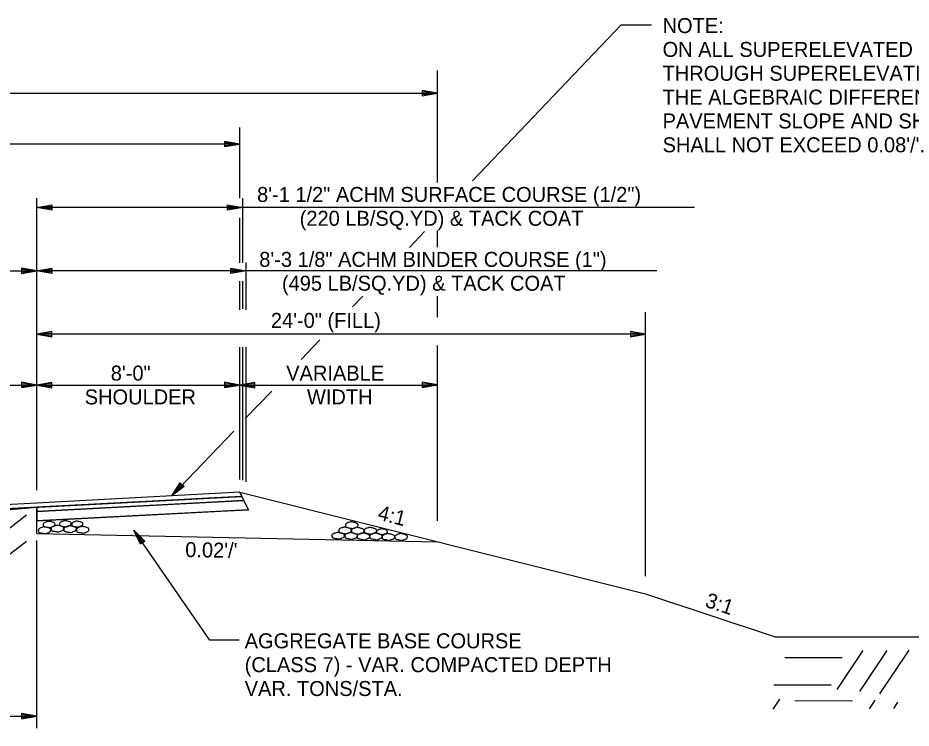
# Model space of a CAD drawing. Extents: x 1398183 to 1398373, y 1967240 to 1968889.
# Drawn here: x 1398269.99 to 1398305.19, y 1967927.15 to 1967955.14 of the extents above; entities that cross this region are included whole.
import ezdxf

# ---------------------------------------------------------------- set-up
doc = ezdxf.new("R2010")
doc.units = 0
for name, color, linetype in [('1', 7, 'Continuous'), ('10', 7, 'Continuous'), ('19', 7, 'Continuous'), ('42', 7, 'Continuous'), ('9', 7, 'Continuous'), ('Level 1', 7, 'Continuous')]:
    doc.layers.add(name, color=color, linetype=linetype)

# ---------------------------------------------------------------- blocks, each defined once
blk = doc.blocks.new('ROCKS')
at = {"layer": '1'}
blk.add_spline([(0.013, 0.06), (0.053, 0.053), (0.107, 0.033), (0.133, 0.013), (0.133, -0.007), (0.12, -0.033), (0.107, -0.04), (0.073, -0.053), (0.033, -0.067), (0.013, -0.067), (-0.02, -0.06), (-0.06, -0.053), (-0.087, -0.047), (-0.113, -0.02), (-0.113, -0.007), (-0.107, 0.02), (-0.087, 0.033), (-0.067, 0.047), (-0.033, 0.053), (-0.02, 0.06), (0.013, 0.06)], degree=3, dxfattribs=at)

msp = doc.modelspace()

# ---------------------------------------------------------------- linework, layer by layer
at = {"layer": '19'}
for p, q in [((1398286.524, 1967948.65), (1398286.524, 1967953.065)), ((1398222.727, 1967952.173), (1398286.524, 1967952.173)), ((1398285.924, 1967952.279), (1398285.924, 1967952.069)), ((1398286.524, 1967952.174), (1398285.924, 1967952.279)), ((1398286.364, 1967952.189), (1398285.924, 1967952.224)), ((1398285.924, 1967952.069), (1398286.524, 1967952.174)), ((1398285.924, 1967952.119), (1398286.364, 1967952.159)), ((1398278.734, 1967948.033), (1398278.734, 1967950.821)), ((1398278.734, 1967950.173), (1398228.734, 1967950.173)), ((1398278.134, 1967950.278), (1398278.134, 1967950.068)), ((1398278.734, 1967950.173), (1398278.134, 1967950.278)), ((1398278.574, 1967950.188), (1398278.134, 1967950.223)), ((1398278.134, 1967950.068), (1398278.734, 1967950.173)), ((1398278.134, 1967950.118), (1398278.574, 1967950.158)), ((1398270.731, 1967936.522), (1398270.731, 1967948.033)), ((1398278.853, 1967945.485), (1398278.853, 1967948.033)), ((1398270.73, 1967947.673), (1398271.33, 1967947.779)), ((1398271.33, 1967947.569), (1398270.73, 1967947.673)), ((1398296.658, 1967947.673), (1398270.73, 1967947.673)), ((1398270.89, 1967947.688), (1398271.33, 1967947.724)), ((1398271.33, 1967947.619), (1398270.89, 1967947.658)), ((1398271.33, 1967947.779), (1398271.33, 1967947.569)), ((1398278.253, 1967947.568), (1398278.253, 1967947.778)), ((1398278.253, 1967947.778), (1398278.853, 1967947.673)), ((1398278.253, 1967947.723), (1398278.693, 1967947.688)), ((1398278.853, 1967947.673), (1398278.253, 1967947.568)), ((1398278.693, 1967947.658), (1398278.253, 1967947.618)), ((1398278.734, 1967945.495), (1398278.734, 1967947.258)), ((1398286.524, 1967946.111), (1398286.524, 1967946.769)), ((1398278.985, 1967943.63), (1398278.985, 1967945.498)), ((1398217.678, 1967945.173), (1398270.731, 1967945.173)), ((1398270.132, 1967945.279), (1398270.132, 1967945.069)), ((1398270.732, 1967945.173), (1398270.132, 1967945.279)), ((1398270.572, 1967945.188), (1398270.132, 1967945.224)), ((1398270.132, 1967945.069), (1398270.732, 1967945.173)), ((1398270.132, 1967945.119), (1398270.572, 1967945.158)), ((1398270.73, 1967945.173), (1398271.33, 1967945.279)), ((1398271.33, 1967945.069), (1398270.73, 1967945.173)), ((1398295.174, 1967945.173), (1398270.73, 1967945.173)), ((1398270.89, 1967945.188), (1398271.33, 1967945.224)), ((1398271.33, 1967945.119), (1398270.89, 1967945.158)), ((1398271.33, 1967945.279), (1398271.33, 1967945.069)), ((1398278.385, 1967945.068), (1398278.385, 1967945.278)), ((1398278.385, 1967945.278), (1398278.985, 1967945.173)), ((1398278.385, 1967945.223), (1398278.825, 1967945.188)), ((1398278.985, 1967945.173), (1398278.385, 1967945.068)), ((1398278.825, 1967945.158), (1398278.385, 1967945.118)), ((1398278.734, 1967943.64), (1398278.734, 1967944.771)), ((1398278.853, 1967943.671), (1398278.853, 1967944.771)), ((1398286.524, 1967943.344), (1398286.524, 1967944.169)), ((1398294.731, 1967933.141), (1398294.731, 1967943.549)), ((1398271.331, 1967942.778), (1398270.731, 1967942.673)), ((1398294.731, 1967942.673), (1398270.731, 1967942.673)), ((1398270.731, 1967942.673), (1398271.331, 1967942.568)), ((1398271.331, 1967942.723), (1398270.891, 1967942.688)), ((1398270.891, 1967942.658), (1398271.331, 1967942.618)), ((1398271.331, 1967942.568), (1398271.331, 1967942.778)), ((1398294.131, 1967942.778), (1398294.131, 1967942.568)), ((1398294.731, 1967942.673), (1398294.131, 1967942.778)), ((1398294.571, 1967942.688), (1398294.131, 1967942.723)), ((1398294.131, 1967942.568), (1398294.731, 1967942.673)), ((1398294.131, 1967942.618), (1398294.571, 1967942.658)), ((1398286.524, 1967935.321), (1398286.524, 1967942.228)), ((1398278.731, 1967936.946), (1398278.731, 1967942.165)), ((1398278.853, 1967936.923), (1398278.853, 1967942.165)), ((1398278.985, 1967936.86), (1398278.985, 1967942.165)), ((1398258.731, 1967940.673), (1398270.731, 1967940.673)), ((1398270.131, 1967940.779), (1398270.131, 1967940.569)), ((1398270.731, 1967940.673), (1398270.131, 1967940.779)), ((1398270.571, 1967940.688), (1398270.131, 1967940.724)), ((1398270.131, 1967940.569), (1398270.731, 1967940.673)), ((1398270.131, 1967940.619), (1398270.571, 1967940.658)), ((1398271.331, 1967940.778), (1398270.731, 1967940.673)), ((1398270.731, 1967940.673), (1398271.331, 1967940.568)), ((1398270.731, 1967940.673), (1398278.731, 1967940.673)), ((1398271.331, 1967940.723), (1398270.891, 1967940.688)), ((1398270.891, 1967940.658), (1398271.331, 1967940.618)), ((1398271.331, 1967940.568), (1398271.331, 1967940.778)), ((1398278.131, 1967940.779), (1398278.131, 1967940.569)), ((1398278.731, 1967940.673), (1398278.131, 1967940.779)), ((1398278.571, 1967940.688), (1398278.131, 1967940.724)), ((1398278.131, 1967940.569), (1398278.731, 1967940.673)), ((1398278.131, 1967940.619), (1398278.571, 1967940.658)), ((1398279.331, 1967940.778), (1398278.731, 1967940.673)), ((1398278.731, 1967940.673), (1398286.524, 1967940.673)), ((1398278.731, 1967940.673), (1398279.331, 1967940.568)), ((1398279.331, 1967940.723), (1398278.891, 1967940.688)), ((1398278.891, 1967940.658), (1398279.331, 1967940.618)), ((1398279.331, 1967940.568), (1398279.331, 1967940.778)), ((1398285.924, 1967940.779), (1398285.924, 1967940.569)), ((1398286.524, 1967940.674), (1398285.924, 1967940.779)), ((1398286.364, 1967940.689), (1398285.924, 1967940.724)), ((1398285.924, 1967940.569), (1398286.524, 1967940.674)), ((1398285.924, 1967940.619), (1398286.364, 1967940.659)), ((1398276.054, 1967936.304), (1398276.386, 1967936.815)), ((1398276.538, 1967936.672), (1398276.054, 1967936.304)), ((1398276.154, 1967936.429), (1398276.423, 1967936.777)), ((1398276.501, 1967936.705), (1398276.175, 1967936.41)), ((1398276.386, 1967936.815), (1398276.538, 1967936.672)), ((1398278.731, 1967936.446), (1398294.731, 1967932.446)), ((1398278.731, 1967936.446), (1398278.813, 1967936.284)), ((1398278.813, 1967936.284), (1398278.894, 1967936.121)), ((1398277.971, 1967936.074), (1398270.731, 1967935.689)), ((1398278.894, 1967936.121), (1398277.971, 1967936.074)), ((1398278.894, 1967936.121), (1398279.077, 1967935.756)), ((1398279.077, 1967935.756), (1398278.894, 1967936.121)), ((1398270.334, 1967935.537), (1398267.632, 1967933.469)), ((1398270.731, 1967934.814), (1398270.731, 1967935.847)), ((1398270.731, 1967935.314), (1398277.99, 1967935.699)), ((1398270.731, 1967935.689), (1398270.731, 1967935.314)), ((1398277.99, 1967935.699), (1398279.077, 1967935.756)), ((1398270.731, 1967934.814), (1398286.524, 1967934.498)), ((1398274.819, 1967934.396), (1398274.566, 1967934.948)), ((1398274.566, 1967934.948), (1398274.991, 1967934.512)), ((1398277.558, 1967930.617), (1398274.566, 1967934.948)), ((1398274.859, 1967934.424), (1398274.642, 1967934.808)), ((1398274.666, 1967934.824), (1398274.946, 1967934.485)), ((1398270.334, 1967934.51), (1398267.652, 1967932.457)), ((1398270.731, 1967927.148), (1398270.731, 1967934.539)), ((1398274.991, 1967934.512), (1398274.819, 1967934.396)), ((1398294.731, 1967932.446), (1398299.832, 1967930.746)), ((1398278.709, 1967930.617), (1398277.558, 1967930.617)), ((1398246.731, 1967927.618), (1398270.731, 1967927.618)), ((1398270.131, 1967927.723), (1398270.131, 1967927.513)), ((1398270.731, 1967927.618), (1398270.131, 1967927.723)), ((1398270.571, 1967927.633), (1398270.131, 1967927.668)), ((1398270.131, 1967927.513), (1398270.731, 1967927.618)), ((1398270.131, 1967927.563), (1398270.571, 1967927.603))]:
    msp.add_line(p, q, dxfattribs=at)
for points in [[(1398294.964, 1967954.862), (1398293.755, 1967954.862), (1398287.901, 1967948.718)], [(1398286.016, 1967946.719), (1398285.418, 1967946.095)], [(1398283.582, 1967944.18), (1398283.174, 1967943.754)], [(1398281.896, 1967942.457), (1398281.158, 1967941.679)], [(1398279.998, 1967940.433), (1398279.998, 1967940.433), (1398278.952, 1967939.347)], [(1398278.495, 1967938.859), (1398278.495, 1967938.859), (1398276.054, 1967936.304)], [(1398278.731, 1967936.446), (1398270.731, 1967936.022), (1398258.731, 1967935.386), (1398246.731, 1967934.75), (1398234.731, 1967934.114), (1398228.731, 1967933.796)], [(1398278.813, 1967936.284), (1398270.731, 1967935.855), (1398258.731, 1967935.219), (1398246.731, 1967934.583), (1398234.731, 1967933.947), (1398228.731, 1967933.629)], [(1398278.894, 1967936.121), (1398270.731, 1967935.689)], [(1398279.077, 1967935.756), (1398270.731, 1967935.314)]]:
    msp.add_lwpolyline(points, dxfattribs=at)
for points in [[(1398228.646, 1967933.626), (1398234.646, 1967933.944), (1398258.722, 1967935.214), (1398270.817, 1967935.852), (1398278.813, 1967936.284), (1398278.731, 1967936.446), (1398270.731, 1967936.022), (1398258.731, 1967935.386), (1398234.731, 1967934.114), (1398228.731, 1967933.796)], [(1398270.731, 1967935.689), (1398276.376, 1967935.989), (1398278.894, 1967936.121), (1398278.813, 1967936.284), (1398277.735, 1967936.227), (1398270.731, 1967935.847)]]:
    msp.add_lwpolyline(points, close=True, dxfattribs=at)
at = {"layer": '42'}
for points in [[(1398270.731, 1967935.841), (1398266.421, 1967935.468), (1398258.785, 1967935.079), (1398249.763, 1967934.595), (1398246.74, 1967934.584), (1398246.731, 1967934.583)], [(1398299.832, 1967930.746), (1398306.118, 1967930.746), (1398309.834, 1967930.695)]]:
    msp.add_lwpolyline(points, dxfattribs=at)
at = {"layer": '9'}
for p, q in [((1398302.48, 1967929.918), (1398300.218, 1967929.924)), ((1398303.287, 1967930.208), (1398302.264, 1967928.674)), ((1398304.239, 1967930.213), (1398303.154, 1967928.586)), ((1398305.099, 1967930.218), (1398303.952, 1967928.498)), ((1398302.041, 1967928.839), (1398299.779, 1967928.845)), ((1398300.004, 1967928.29), (1398299.74, 1967927.894)), ((1398302.878, 1967928.213), (1398300.616, 1967928.219)), ((1398303.768, 1967928.256), (1398303.541, 1967927.915)), ((1398304.658, 1967928.168), (1398304.493, 1967927.92))]:
    msp.add_line(p, q, dxfattribs=at)

# ---------------------------------------------------------------- block references
at = {"layer": 'Level 1'}
for p, xscale, yscale, rotation in [((1398271.201, 1967935.184), 1.8866375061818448, 1.886637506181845, 1.8263814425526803), ((1398271.842, 1967935.208), 1.851115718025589, 1.851115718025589, 1.8263814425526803), ((1398272.317, 1967935.195), 1.773922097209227, 1.773922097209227, 1.8263814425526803), ((1398283.133, 1967935.154), 2.011654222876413, 2.0116542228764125, -0.17361855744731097), ((1398271.023, 1967934.953), 2.011654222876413, 2.011654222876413, 1.8263814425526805), ((1398271.531, 1967935.016), 2.011654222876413, 2.011654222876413, 1.8263814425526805), ((1398272.025, 1967934.997), 2.011654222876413, 2.011654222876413, 1.8263814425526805), ((1398272.522, 1967934.972), 2.011654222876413, 2.011654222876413, 1.8263814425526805), ((1398282.594, 1967934.739), 2.011654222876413, 2.0116542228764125, -0.17361855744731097), ((1398282.594, 1967934.739), 2.011654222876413, 2.0116542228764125, -0.17361855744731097), ((1398282.864, 1967934.946), 2.011654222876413, 2.0116542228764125, -0.17361855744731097), ((1398283.098, 1967934.729), 2.011654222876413, 2.0116542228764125, -0.17361855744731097), ((1398283.098, 1967934.729), 2.011654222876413, 2.0116542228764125, -0.17361855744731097), ((1398283.364, 1967934.934), 2.011654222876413, 2.0116542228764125, -0.17361855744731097), ((1398283.59, 1967934.711), 2.011654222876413, 2.0116542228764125, -0.17361855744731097), ((1398283.59, 1967934.711), 2.011654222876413, 2.0116542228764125, -0.17361855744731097), ((1398283.86, 1967934.934), 2.011654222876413, 2.0116542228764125, -0.17361855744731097), ((1398284.08, 1967934.711), 2.011654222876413, 2.0116542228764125, -0.17361855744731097), ((1398284.08, 1967934.711), 2.011654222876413, 2.0116542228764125, -0.17361855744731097), ((1398284.322, 1967934.895), 1.7335100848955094, 1.7335100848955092, -0.173618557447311), ((1398284.574, 1967934.691), 2.011654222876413, 2.0116542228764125, -0.17361855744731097), ((1398284.574, 1967934.691), 2.011654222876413, 2.0116542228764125, -0.17361855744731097), ((1398285.076, 1967934.691), 2.011654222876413, 2.0116542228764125, -0.17361855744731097), ((1398285.076, 1967934.691), 2.011654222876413, 2.0116542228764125, -0.17361855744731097)]:
    msp.add_blockref('ROCKS', p, dxfattribs=dict(at, xscale=xscale, yscale=yscale, rotation=rotation))

# ---------------------------------------------------------------- texts
at = {"layer": '10'}
for s, height, p in [('24\'-0" (FILL)', 0.59001, (1398279.962, 1967942.925)), ('8\'-0"', 0.59, (1398273.651, 1967940.848)), ('VARIABLE', 0.59, (1398280.565, 1967940.848)), ('SHOULDER', 0.59, (1398272.624, 1967939.908)), ('WIDTH', 0.59, (1398281.383, 1967939.908))]:
    msp.add_text(s, height=height, dxfattribs=at).set_placement(p)
for s, rotation, p in [('4:1', 345.9638, (1398284.134, 1967935.371)), ('3:1', 341.5868, (1398297.036, 1967931.943))]:
    msp.add_text(s, height=0.59, rotation=rotation, dxfattribs=at).set_placement(p)
at = {"layer": '19'}
for s, height, p in [('NOTE:', 0.59, (1398295.399, 1967954.546)), ('ON ALL SUPERELEVATED CURVES AND', 0.59001, (1398295.399, 1967953.606)), ('THROUGH SUPERELEVATION TRANSITIONS,', 0.59001, (1398295.399, 1967952.666)), ('THE ALGEBRAIC DIFFERENCE BETWEEN', 0.59001, (1398295.399, 1967951.726)), ('PAVEMENT SLOPE AND SHOULDER SLOPE', 0.59001, (1398295.399, 1967950.786)), ("SHALL NOT EXCEED 0.08'/'.", 0.59001, (1398295.399, 1967949.846))]:
    msp.add_text(s, height=height, dxfattribs=at).set_placement(p)
for s, height, rotation, p in [("0.02'/'", 0.59, 358.8542, (1398276.581, 1967933.895)), ('AGGREGATE BASE COURSE', 0.59001, 360, (1398278.929, 1967930.295)), ('(CLASS 7) - VAR. COMPACTED DEPTH', 0.59001, 360, (1398278.929, 1967929.355)), ('VAR. TONS/STA.', 0.59001, 360, (1398278.929, 1967928.415))]:
    msp.add_text(s, height=height, rotation=rotation, dxfattribs=at).set_placement(p)
at = {"layer": '42'}
for s, p in [('8\'-1 1/2" ACHM SURFACE COURSE (1/2")', (1398279.417, 1967947.889)), ('(220 LB/SQ.YD) & TACK COAT', (1398281.097, 1967946.949)), ('8\'-3 1/8" ACHM BINDER COURSE (1")', (1398279.503, 1967945.331)), ('(495 LB/SQ.YD) & TACK COAT', (1398280.397, 1967944.391))]:
    msp.add_text(s, height=0.59001, rotation=360, dxfattribs=at).set_placement(p)

doc.saveas('drawing.dxf')
